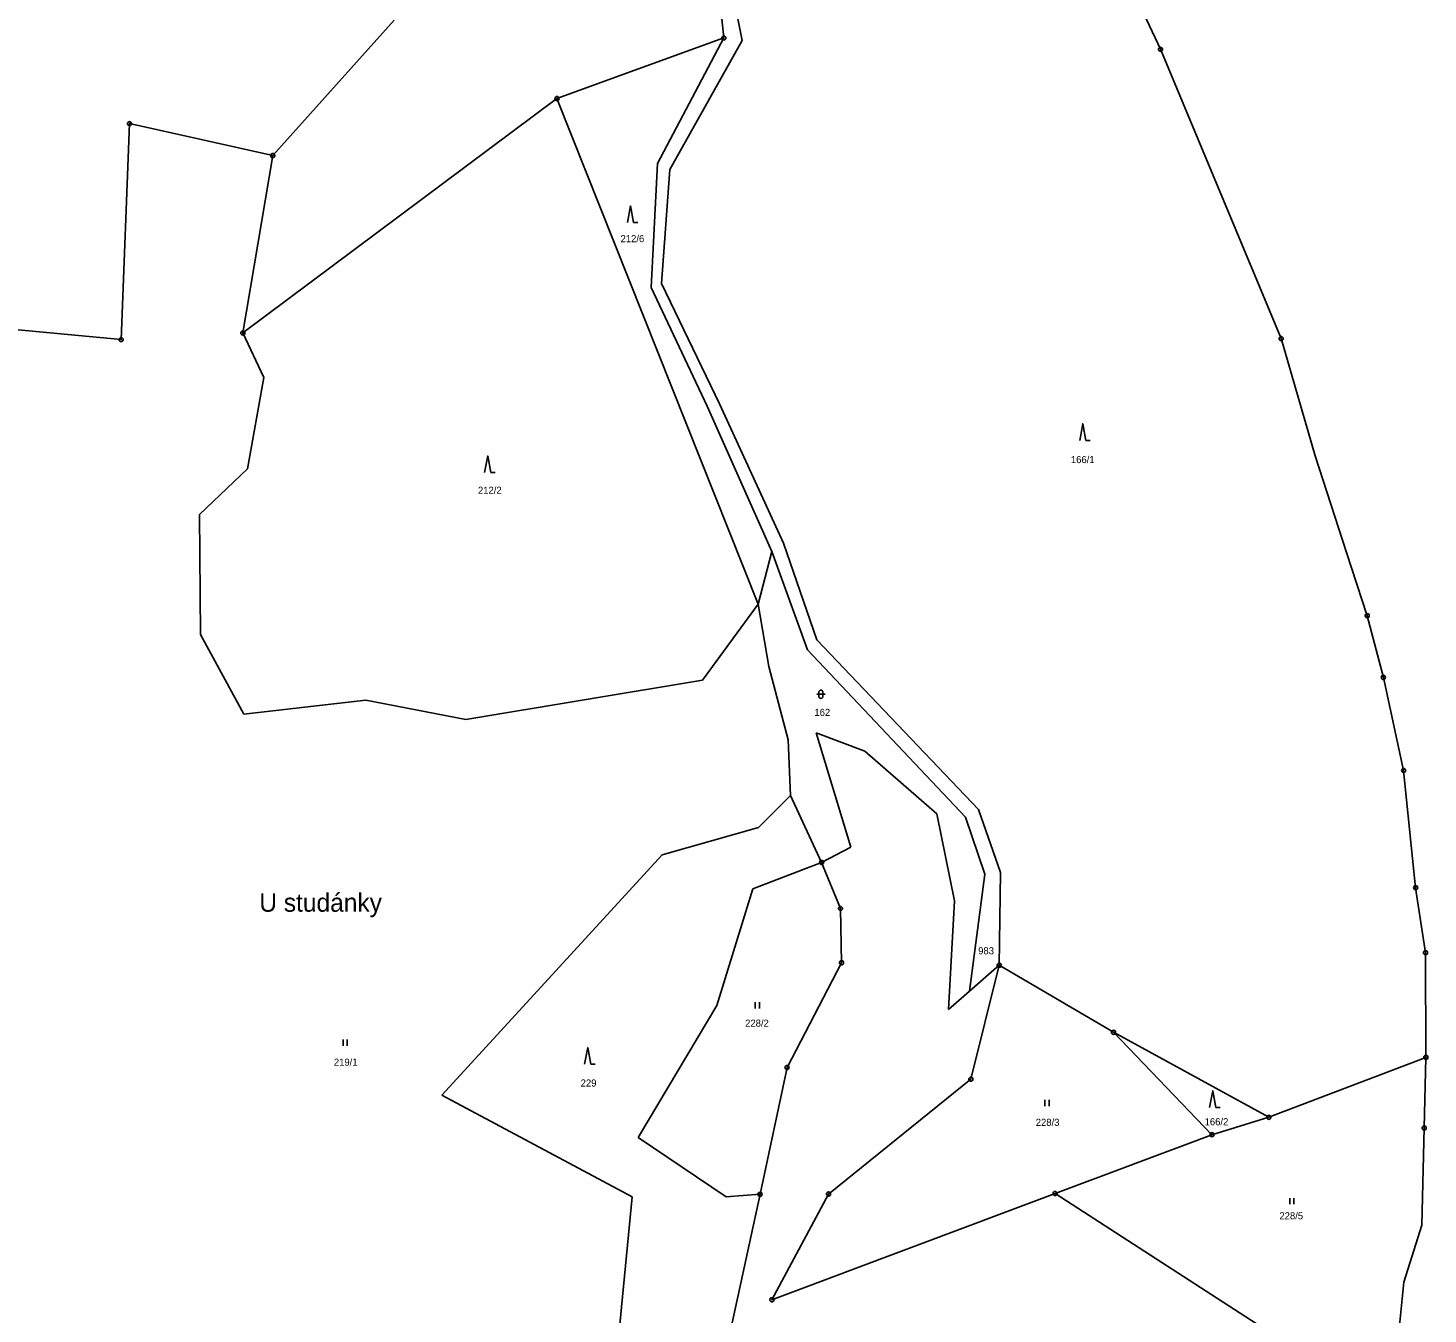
# Model space of a CAD drawing. Extents: x -754970 to -752637, y -970569 to -968179.
# Drawn here: x -752973.4 to -752637.4, y -969218.4 to -968909.9 of the extents above; entities that cross this region are included whole.
import ezdxf
from ezdxf.enums import TextEntityAlignment as Align

# ---------------------------------------------------------------- set-up
doc = ezdxf.new("R2010")
doc.units = 0
doc.header["$LTSCALE"] = 0.68
for name, color, linetype, lineweight in [('1', 7, 'Continuous', 25), ('3', 7, 'Continuous', 25), ('7', 7, 'Continuous', 13), ('8', 7, 'Continuous', 25)]:
    doc.layers.add(name, color=color, linetype=linetype, lineweight=lineweight)
doc.layers.add('2', color=7, linetype='Continuous')

msp = doc.modelspace()

# ---------------------------------------------------------------- linework, layer by layer
at = {"layer": '1'}
for p, q in [((-752717.72, -968880.63), (-752701.62, -968915.01)), ((-752808.43, -968892.55), (-752806.42, -968912.28)), ((-752806.55, -968889.54), (-752802.03, -968912.88)), ((-752885.55, -968908.04), (-752914.67, -968940.51)), ((-752806.42, -968912.28), (-752846.46, -968926.83)), ((-752806.42, -968912.28), (-752822.35, -968942.41)), ((-752802.03, -968912.88), (-752819.38, -968943.84)), ((-752701.62, -968915.01), (-752672.66, -968984.4)), ((-752846.46, -968926.83), (-752921.84, -968983.07)), ((-752846.46, -968926.83), (-752798.2, -969048.13)), ((-752949.05, -968932.84), (-752951.05, -968984.64)), ((-752914.67, -968940.51), (-752949.05, -968932.84)), ((-752914.67, -968940.51), (-752921.84, -968983.07)), ((-752822.35, -968942.41), (-752823.87, -968972.17)), ((-752819.38, -968943.84), (-752821.38, -968971.18)), ((-752823.87, -968972.17), (-752810.45, -969000.59)), ((-752951.05, -968984.64), (-752981.53, -968981.79)), ((-752916.82, -968993.72), (-752921.84, -968983.07)), ((-752672.66, -968984.4), (-752664.47, -969012.57)), ((-752920.72, -969015.63), (-752916.82, -968993.72)), ((-752810.45, -969000.59), (-752794.86, -969035.5)), ((-752664.47, -969012.57), (-752656.97, -969035.76)), ((-752932.23, -969026.58), (-752920.72, -969015.63)), ((-752932.05, -969055.37), (-752932.23, -969026.58)), ((-752792.07, -969033.46), (-752784.09, -969056.67)), ((-752798.2, -969048.13), (-752794.86, -969035.5)), ((-752794.86, -969035.5), (-752786.32, -969059.08)), ((-752656.97, -969035.76), (-752652.01, -969050.88)), ((-752798.2, -969048.13), (-752811.57, -969066.33)), ((-752795.65, -969063.05), (-752798.2, -969048.13)), ((-752652.01, -969050.88), (-752648.13, -969065.7)), ((-752921.65, -969074.49), (-752932.05, -969055.37)), ((-752784.09, -969056.67), (-752745.29, -969097.34)), ((-752786.32, -969059.08), (-752748.45, -969099.2)), ((-752790.96, -969080.63), (-752795.65, -969063.05)), ((-752811.57, -969066.33), (-752868.37, -969075.79)), ((-752648.13, -969065.7), (-752643.27, -969088.02)), ((-752892.32, -969071.15), (-752921.65, -969074.49)), ((-752868.37, -969075.79), (-752892.32, -969071.15)), ((-752790.4, -969094), (-752790.96, -969080.63)), ((-752784.28, -969078.95), (-752775.92, -969106.44)), ((-752772.58, -969083.41), (-752784.28, -969078.95)), ((-752755.31, -969098.45), (-752772.58, -969083.41)), ((-752643.27, -969088.02), (-752640.38, -969116.14)), ((-752790.4, -969094), (-752798.12, -969101.69)), ((-752782.94, -969110.08), (-752790.4, -969094)), ((-752745.29, -969097.34), (-752740.04, -969112.52)), ((-752751.04, -969119.25), (-752755.31, -969098.45)), ((-752748.45, -969099.2), (-752743.74, -969112.9)), ((-752798.12, -969101.69), (-752821.25, -969108.21)), ((-752775.92, -969106.44), (-752782.94, -969110.08)), ((-752821.25, -969108.21), (-752874.13, -969165.91)), ((-752782.94, -969110.08), (-752799.46, -969116.39)), ((-752782.94, -969110.08), (-752778.42, -969121.12)), ((-752747.42, -969140.92), (-752743.74, -969112.9)), ((-752740.04, -969112.52), (-752740.32, -969134.73)), ((-752799.46, -969116.39), (-752808.13, -969144.41)), ((-752640.38, -969116.14), (-752638.01, -969131.72)), ((-752778.42, -969121.12), (-752778.16, -969134.14)), ((-752752.47, -969145.32), (-752751.04, -969119.25)), ((-752778.16, -969134.14), (-752791.24, -969159.26)), ((-752638.01, -969131.72), (-752637.92, -969156.83)), ((-752740.32, -969134.73), (-752747.42, -969140.92)), ((-752740.32, -969134.73), (-752747.12, -969162.06)), ((-752712.88, -969150.82), (-752740.32, -969134.73)), ((-752747.42, -969140.92), (-752752.47, -969145.32)), ((-752808.13, -969144.41), (-752826.96, -969176.03)), ((-752689.27, -969175.38), (-752712.88, -969150.82)), ((-752712.88, -969150.82), (-752675.62, -969171.21)), ((-752675.62, -969171.21), (-752637.92, -969156.83)), ((-752637.92, -969156.83), (-752638.32, -969173.76)), ((-752797.72, -969189.68), (-752791.24, -969159.26)), ((-752747.12, -969162.06), (-752781.28, -969189.62)), ((-752874.13, -969165.91), (-752828.45, -969190.26)), ((-752675.62, -969171.21), (-752689.27, -969175.38)), ((-752638.86, -969197.08), (-752638.32, -969173.76)), ((-752726.91, -969189.49), (-752689.27, -969175.38)), ((-752828.45, -969190.26), (-752831.82, -969225.84)), ((-752797.72, -969189.68), (-752804.81, -969222.34)), ((-752726.91, -969189.49), (-752794.88, -969214.98)), ((-752781.28, -969189.62), (-752794.88, -969214.98)), ((-752651.63, -969238.09), (-752726.91, -969189.49)), ((-752643.23, -969210.72), (-752638.86, -969197.08)), ((-752644.98, -969228.36), (-752643.23, -969210.72))]:
    msp.add_line(p, q, dxfattribs=at)
for points in [[(-752821.38, -968971.18), (-752807.48, -969000.03), (-752792.07, -969033.46)], [(-752826.96, -969176.03), (-752805.87, -969190.26), (-752797.72, -969189.68)]]:
    msp.add_lwpolyline(points, dxfattribs=at)
at = {"layer": '3'}
for p, q in [((-752828.07, -968956.59), (-752827.074, -968956.59)), ((-752719.51, -969008.85), (-752718.514, -969008.85)), ((-752862.32, -969016.55), (-752861.324, -969016.55)), ((-752784.131, -969069.741), (-752782.129, -969069.741)), ((-752783.631, -969069.241), (-752783.631, -969070.242)), ((-752782.629, -969070.242), (-752782.629, -969069.241)), ((-752798.871, -969145.12), (-752798.871, -969143.62)), ((-752797.87, -969145.12), (-752797.87, -969143.62)), ((-752897.781, -969154.03), (-752897.781, -969152.53)), ((-752896.78, -969154.03), (-752896.78, -969152.53)), ((-752838.33, -969158.47), (-752837.334, -969158.47)), ((-752729.351, -969168.51), (-752729.351, -969167.01)), ((-752728.35, -969168.51), (-752728.35, -969167.01)), ((-752688.32, -969168.82), (-752687.324, -969168.82)), ((-752670.591, -969192.08), (-752670.591, -969190.58)), ((-752669.59, -969192.08), (-752669.59, -969190.58))]:
    msp.add_line(p, q, dxfattribs=at)
for points in [[(-752828.07, -968956.59), (-752828.82, -968952.59), (-752829.57, -968956.59)], [(-752719.51, -969008.85), (-752720.26, -969004.85), (-752721.01, -969008.85)], [(-752862.32, -969016.55), (-752863.07, -969012.55), (-752863.82, -969016.55)], [(-752838.33, -969158.47), (-752839.08, -969154.47), (-752839.83, -969158.47)], [(-752688.32, -969168.82), (-752689.07, -969164.82), (-752689.82, -969168.82)]]:
    msp.add_lwpolyline(points, dxfattribs=at)
for centre, start, end in [((-752783.13, -969069.2409), 0, 180), ((-752783.13, -969070.2409), 180, 359.98789)]:
    msp.add_arc(centre, 0.5, start, end, dxfattribs=at)
at = {"layer": '8'}
for centre, radius in [((-752806.42, -968912.2799), 0.5), ((-752806.42, -968912.2799), 0.0303), ((-752701.62, -968915.0099), 0.5), ((-752701.62, -968915.0099), 0.0303), ((-752846.46, -968926.8299), 0.5), ((-752846.46, -968926.8299), 0.0303), ((-752949.05, -968932.8399), 0.5), ((-752949.05, -968932.8399), 0.0303), ((-752914.67, -968940.5099), 0.5), ((-752914.67, -968940.5099), 0.0303), ((-752921.84, -968983.0699), 0.5), ((-752921.84, -968983.0699), 0.0303), ((-752951.05, -968984.6399), 0.5), ((-752951.05, -968984.6399), 0.0303), ((-752672.66, -968984.3999), 0.5), ((-752672.66, -968984.3999), 0.0303), ((-752652.01, -969050.8799), 0.5), ((-752652.01, -969050.8799), 0.0303), ((-752648.13, -969065.6999), 0.5), ((-752648.13, -969065.6999), 0.0303), ((-752643.27, -969088.0199), 0.5), ((-752643.27, -969088.0199), 0.0303), ((-752782.94, -969110.0799), 0.5), ((-752782.94, -969110.0799), 0.0303), ((-752640.38, -969116.1399), 0.5), ((-752640.38, -969116.1399), 0.0303), ((-752778.42, -969121.1199), 0.5), ((-752778.42, -969121.1199), 0.0303), ((-752638.01, -969131.7199), 0.5), ((-752778.16, -969134.1399), 0.5), ((-752778.16, -969134.1399), 0.0303), ((-752740.32, -969134.7299), 0.5), ((-752638.01, -969131.7199), 0.0303), ((-752740.32, -969134.7299), 0.0303), ((-752712.88, -969150.8199), 0.5), ((-752712.88, -969150.8199), 0.0303), ((-752637.92, -969156.8299), 0.5), ((-752637.92, -969156.8299), 0.0303), ((-752791.24, -969159.2599), 0.5), ((-752791.24, -969159.2599), 0.0303), ((-752747.12, -969162.0599), 0.5), ((-752747.12, -969162.0599), 0.0303), ((-752675.62, -969171.2099), 0.5), ((-752675.62, -969171.2099), 0.0303), ((-752689.27, -969175.3799), 0.5), ((-752638.32, -969173.7599), 0.5), ((-752638.32, -969173.7599), 0.0303), ((-752689.27, -969175.3799), 0.0303), ((-752797.72, -969189.6799), 0.5), ((-752797.72, -969189.6799), 0.0303), ((-752781.28, -969189.6199), 0.5), ((-752781.28, -969189.6199), 0.0303), ((-752726.91, -969189.4899), 0.5), ((-752726.91, -969189.4899), 0.0303), ((-752794.88, -969214.9799), 0.5), ((-752794.88, -969214.9799), 0.0303)]:
    msp.add_circle(centre, radius, dxfattribs=at)

# ---------------------------------------------------------------- texts
at = {"layer": '2'}
for s, p in [('212/6', (-752828.36, -968961.285)), ('166/1', (-752720.28, -969014.285)), ('212/2', (-752862.58, -969021.645)), ('162', (-752782.779, -969074.925)), ('983', (-752743.479, -969132.115)), ('228/2', (-752798.46, -969149.475)), ('219/1', (-752897.16, -969158.825)), ('229', (-752838.879, -969163.835)), ('228/3', (-752728.71, -969173.265)), ('228/5', (-752670.24, -969195.685))]:
    msp.add_text(s, height=1.7, dxfattribs=at).set_placement(p, align=Align.CENTER)
msp.add_text('166/2', height=1.7, dxfattribs=at).set_placement((-752691.03, -969173.125))
at = {"layer": '7'}
msp.add_text('U studánky', height=4.4, dxfattribs=at).set_placement((-752917.9, -969121.9))

doc.saveas('drawing.dxf')
